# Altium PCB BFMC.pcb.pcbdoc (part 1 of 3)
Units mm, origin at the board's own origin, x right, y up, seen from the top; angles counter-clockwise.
Board outline 121.38 x 89.66 mm, 2 copper layers (Top Layer, Bottom Layer); 106 components, 51 nets, 277 pads, 97 vias.
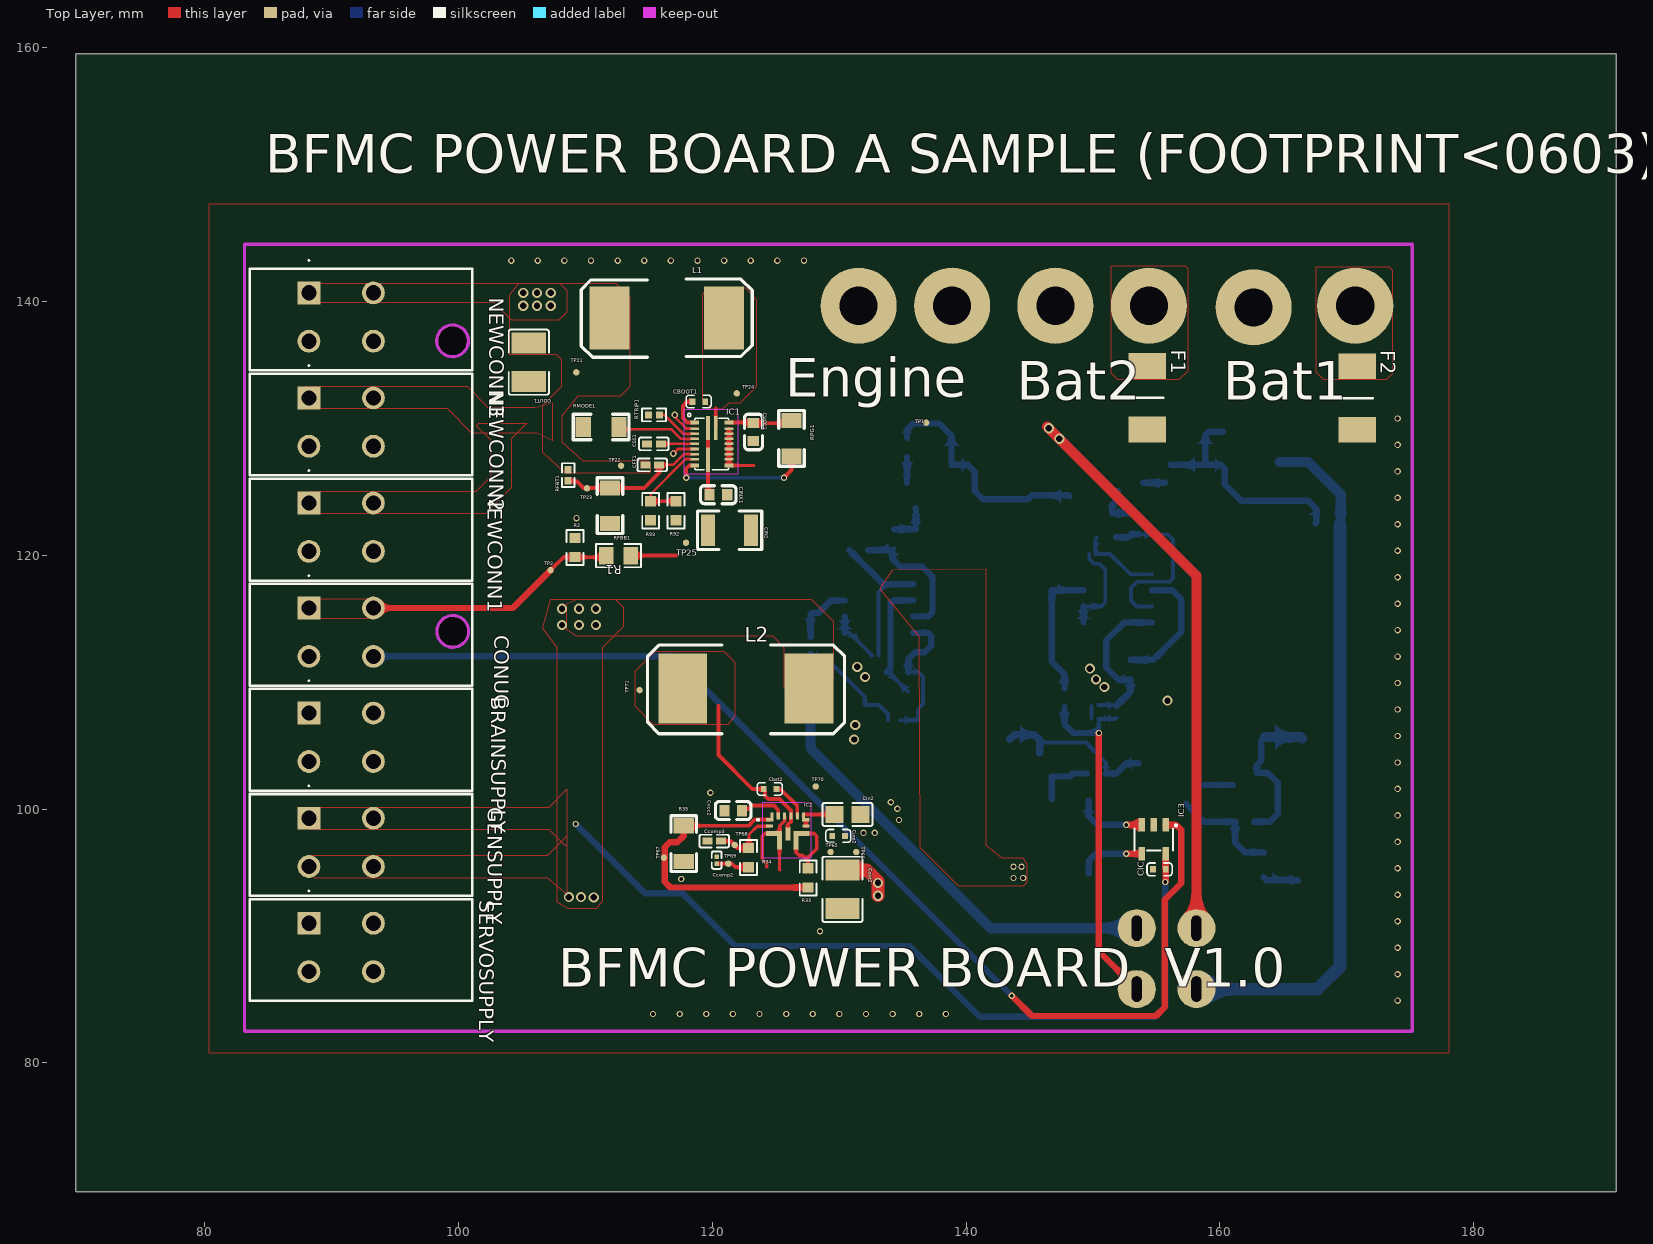
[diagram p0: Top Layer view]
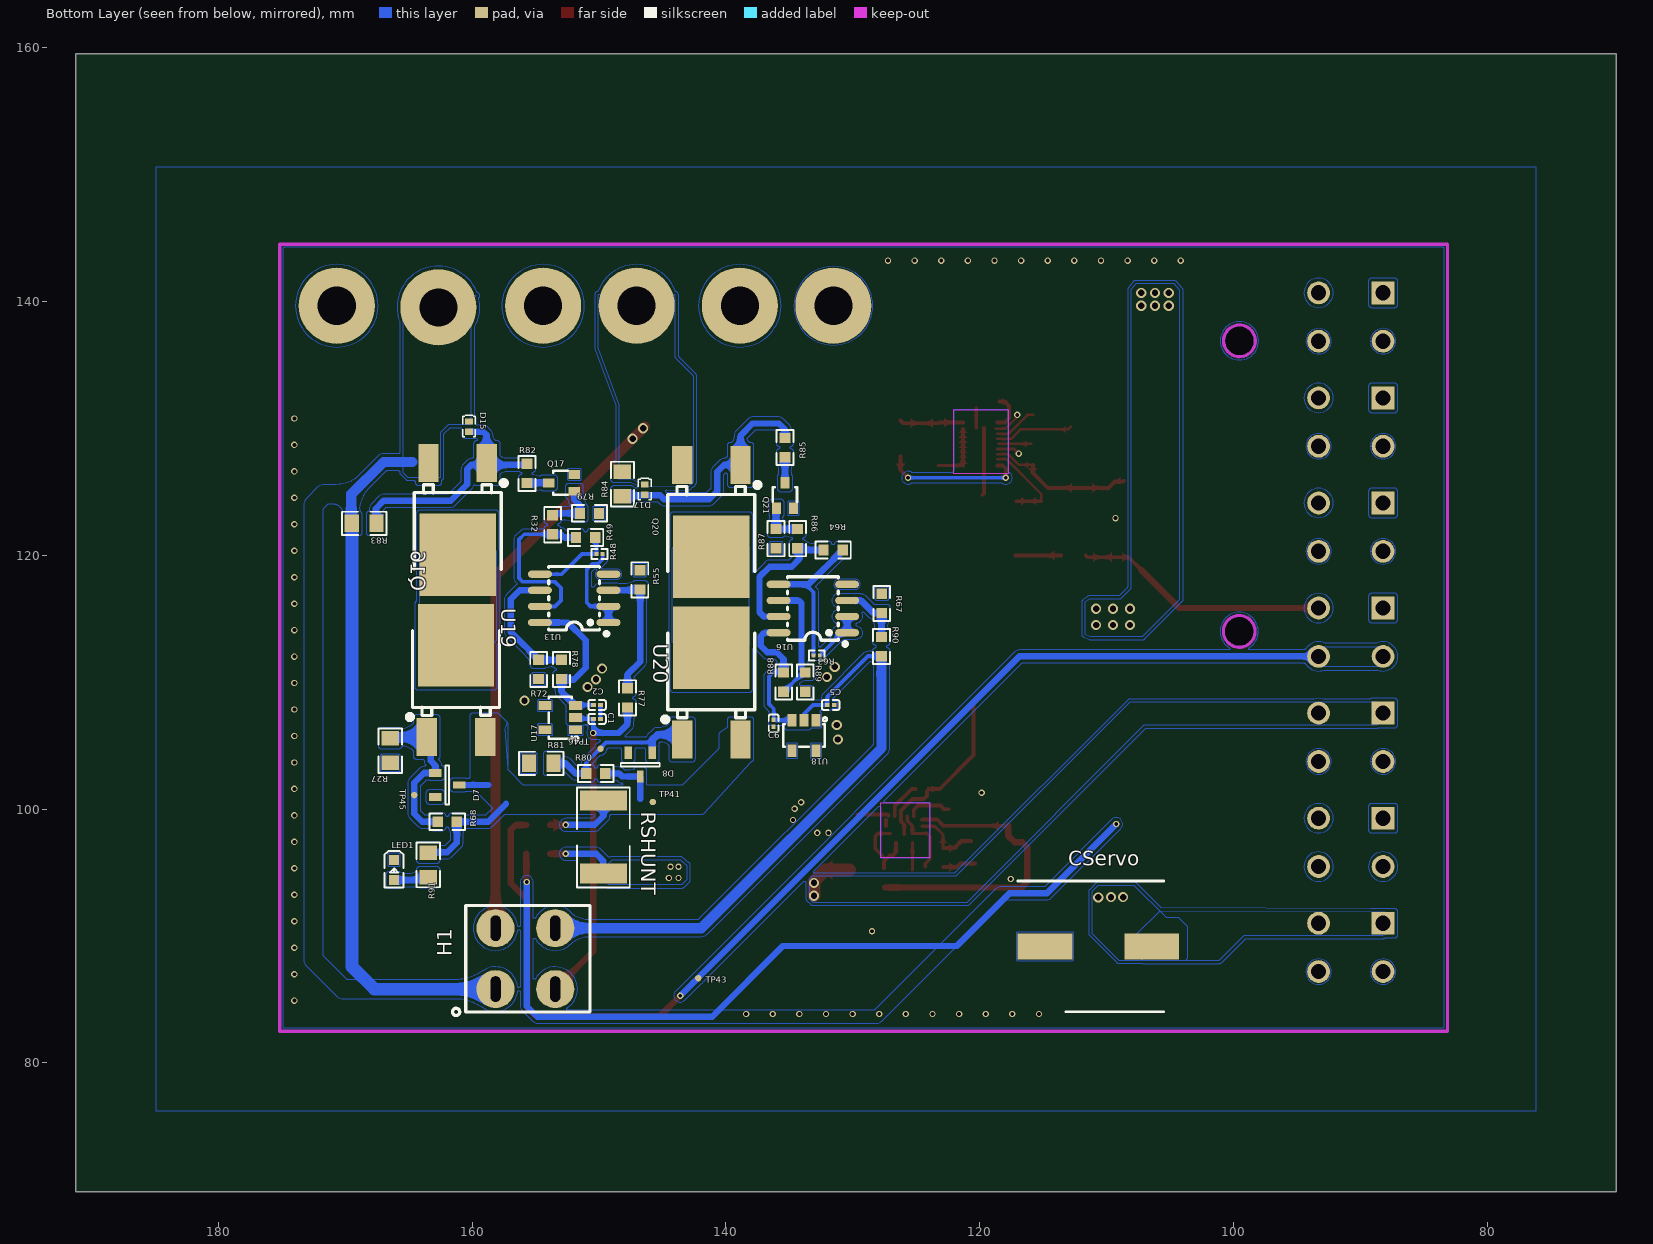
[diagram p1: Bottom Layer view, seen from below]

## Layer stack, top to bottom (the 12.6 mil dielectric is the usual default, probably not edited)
Top Layer: signal copper (thickness not stored)
Dielectric: dielectric 0.32, FR-4, Dk 4.8
Bottom Layer: signal copper (thickness not stored)

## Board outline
191.233,69.85 69.85,69.85 69.85,159.511 191.233,159.511
cut-out: 100.797,136.879 ccw(c99.547,136.867) 98.297,136.879 ccw(c99.547,136.89)
cut-out: 100.814,113.992 ccw(c99.564,113.979) 98.314,113.992 ccw(c99.564,114.004)

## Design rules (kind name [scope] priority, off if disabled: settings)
Clearance copperThickness1oz [All] p1: gap=0.178 ignorepadtopadclearanceinfootprint=FALSE except(0.102: Track-Track; 0.152: Track-SMDPad SMDPad-SMDPad Track-THPad SMDPad-THPad THPad-THPad Track-Via SMDPad-Via THPad-Via Via-Via Track-Fill SMDPad-Fill THPad-Fill Via-Fill Fill-Fill SMDPad-Region THPad-Region Via-Region Fill-Region Region-Region Track-Poly SMDPad-Poly THPad-Poly Via-Poly Fill-Poly Poly-Poly Track-Text SMDPad-Text THPad-Text Via-Text Fill-Text Region-Text Poly-Text Text-Text Track-Hole SMDPad-Hole THPad-Hole Via-Hole Fill-Hole Region-Hole Poly-Hole Text-Hole; 0.3: Track-Region Region-Poly Track-Sheet SMDPad-Sheet THPad-Sheet Via-Sheet Fill-Sheet Region-Sheet Poly-Sheet Text-Sheet Sheet-Hole)
Clearance copperThickness2oz [All] p1: gap=0.178 ignorepadtopadclearanceinfootprint=FALSE except(0.152: Track-SMDPad SMDPad-SMDPad Track-THPad SMDPad-THPad THPad-THPad Track-Via SMDPad-Via THPad-Via Via-Via Track-Fill SMDPad-Fill THPad-Fill Via-Fill Fill-Fill SMDPad-Region THPad-Region Via-Region Fill-Region Region-Region Track-Poly SMDPad-Poly THPad-Poly Via-Poly Fill-Poly Poly-Poly Track-Text SMDPad-Text THPad-Text Via-Text Fill-Text Region-Text Poly-Text Text-Text Track-Hole SMDPad-Hole THPad-Hole Via-Hole Fill-Hole Region-Hole Poly-Hole Text-Hole; 0.203: Track-Track; 0.3: Track-Region Region-Poly Track-Sheet SMDPad-Sheet THPad-Sheet Via-Sheet Fill-Sheet Region-Sheet Poly-Sheet Text-Sheet Sheet-Hole)
Clearance Supply-GND [All] p1: gap=0.178 ignorepadtopadclearanceinfootprint=FALSE except(0.5: Track-Track Track-SMDPad SMDPad-SMDPad Track-THPad SMDPad-THPad THPad-THPad Track-Via SMDPad-Via THPad-Via Via-Via Track-Fill SMDPad-Fill THPad-Fill Via-Fill Fill-Fill Track-Region SMDPad-Region THPad-Region Via-Region Fill-Region Region-Region Track-Poly SMDPad-Poly THPad-Poly Via-Poly Fill-Poly Region-Poly Poly-Poly Track-Text SMDPad-Text THPad-Text Via-Text Fill-Text Region-Text Poly-Text Text-Text Track-Sheet SMDPad-Sheet THPad-Sheet Via-Sheet Fill-Sheet Region-Sheet Poly-Sheet Text-Sheet Track-Hole SMDPad-Hole THPad-Hole Via-Hole Fill-Hole Region-Hole Poly-Hole Text-Hole Sheet-Hole)
DiffPairsRouting differentialPair [All] p1: maxuncoupledlength=10 maxlimit=5.9843 mostfreqgap=5.9843 toplayer_minwidth=5 toplayer_prefwidth=10 toplayer_maxwidth=100 bottomlayer_minwidth=5 bottomlayer_prefwidth=10 bottomlayer_maxwidth=100
PasteMaskExpansion pasteMaskExpansion [All] p1:
PlaneConnect innerPlane [All] p1: planeconnectstyle=Relief reliefexpansion=0.508 reliefentries=4 reliefconductorwidth=0.254 reliefairgap=0.254
PolygonConnect copperRegion [All] p1: connectstyle=Direct reliefentries=4 reliefconductorwidth=10 polygonreliefangle="90 Angle" airgapwidth=10
PolygonConnect copperRegion1 [All] p1: connectstyle=Relief reliefentries=4 reliefconductorwidth=10 polygonreliefangle="90 Angle" airgapwidth=10
PolygonConnect copperRegion2 [All] p1: connectstyle=Relief reliefentries=4 reliefconductorwidth=10 polygonreliefangle="90 Angle" airgapwidth=10
RoutingVias viaSize [All] p1: viastyle="Through Hole" holewidth=12.0078 minholewidth=11.811 maxholewidth=248.0314 width=24.0158 minwidth=19.685 maxwidth=393.7008
SolderMaskExpansion solderMaskExpansion [All] p1: useseparateexpansions=TRUE expansion=2.0079 expansionbottom=2.0079
Width copperThickness1oz [All] p1: maxlimit=100 minlimit=5 preferedwidth=10
Width copperThickness2oz [All] p1: maxlimit=100 minlimit=8 preferedwidth=10

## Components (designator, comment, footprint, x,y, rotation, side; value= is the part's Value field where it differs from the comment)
BRAINSUPPLY "switch" 1704498 88.231,107.554 r270 top
C1 "CAP_0201" c0201 150.151,107.096 r180 bottom
C2 "CAP_0201" c0201 150.151,108.196 r180 bottom
C5 "CAP_0201" c0201 131.751,108.196 r180 bottom
C6 "CAP_0201" C0201 136.237,106.753 r270 bottom
CBOOT1 "EMK105 B7104KVHF" "emk105 b7104kvhf" 118.951,132.096 r0 top
Cbst2 "CAP_0201" "EMK105 B7104KVHF" 124.558,101.575 r0 top
Ccomp2 "CAP_0201" c0201 120.358,95.975 r270 top
Ccomp3 "CAP_0201" c0402 120.158,97.475 r0 top
CFF1 "C1005C0G1H220J" c0402_new 115.277,127.108 r0 top
CIC "C2012X7S1C106K" "emk105 b7104kvhf" 155.22,95.256 r180 top
CIN1 "GCJ31CC71E106K" r1206-1 121.373,121.963 r0 top
Cin2 "CAP_0201" c0805 130.658,99.575 r180 top
CINX1 "GCM188C71A225K" c0603 120.484,124.757 r0 top
Cinx2 "CAP_0201" "emk105 b7104kvhf" 129.958,97.875 r0 top
CONUC "switch" 1704498 88.231,115.831 r270 top
COUT1 "EMK325ABJ107MM-T" c1210 105.551,135.196 r270 top
Cout2 "CAP_0201" c1210 130.258,93.675 r90 top
CServo "GCM188C71A225K" capae1030x1050n 110.665,89.178 r180 bottom
CSS1 "C1608X7R1H154K" c0402_new 115.404,128.759 r180 top
CVCC1 "GCM188C71A225K" c0603 123.251,129.696 r270 top
Cvcc2 "CAP_0201" C0603 121.658,99.875 r0 top
D7 "SZBZX84C18ET1G" szbzx84c18et1g 161.951,101.896 r270 bottom
D8 "SZBZX84C18ET1G" szbzx84c18et1g 146.751,103.496 r0 bottom
D15 "PZU6.8B2L,315" dfn1006-2l-rd 160.24,130.121 r270 bottom
D17 "PZU6.8B2L,315" dfn1006-2l-rd 146.397,125.168 r270 bottom
F1 "0451015.MRL" fusc6127x294n 154.271,132.399 r270 top
F2 "0451015.MRL" fusc6127x294n 170.799,132.372 r270 top
GENSUPPLY "switch" 1704498 88.231,99.277 r270 top
H1 "switch" M2021BB1W01 155.795,88.211 r0 bottom
IC1 "TPS548A28RWWR" TPS548B28RWWR 119.976,128.759 r0 top
IC2 "TPS61288RQQR" TPS61288RQQR 125.958,98.275 r0 top
IC3 "INA180A2QDBVRQ1" ina180a2qdbvrq1 154.779,97.609 r180 top
L1 "IHLP4040DZERR47M11" ihlp4040dzerr47m11 116.42,138.63 r0 top
L2 "L_0402" "dr127-3r3-r (l2)" 122.658,109.488 r0 top
LED1 "19-213/Y2C-CQ2R2L/3T(CY)" led0603-rd-yellow 166.151,95.196 r270 bottom
NEWCONN1 "switch" 1704498 88.231,124.108 r270 top
NEWCONN2 "switch" 1704498 88.231,132.385 r270 top
NEWCONN3 "switch" 1704498 88.231,140.662 r270 top
Q16 "IPD50P04P4-13" pg-to252-3_l6.3-w6.5-p4.57-ls10.0-br-cw 161.129,123.644 r90 bottom
Q17 "BC846W" sot-323-3_l2.2-w1.3-p1.30-ls2.2-br 152.951,125.696 r180 bottom
Q20 "IPD50P04P4-13" pg-to252-3_l6.3-w6.5-p4.57-ls10.0-br-cw 141.151,123.496 r90 bottom
Q21 "BC846W" sot-323-3_l2.2-w1.3-p1.30-ls2.2-br 135.351,124.696 r270 bottom
R1 "MCR03..PFX1051" R0805_NEW 112.615,119.961 r0 top
R2 "MCR03...PFX7680" r0603_new 109.186,120.596 r90 top
R27 "MCR03..PFX1002" r0805_new 166.451,104.596 r270 bottom
R32 "MCR03..PFX1002" R0603 153.651,122.396 r90 bottom
R33 "MCR03..PFX1002" r0603 127.558,94.575 r90 top
R34 "MCR03..PFX1002" R0603 122.858,96.175 r90 top
R35 "MCR03..PFX1002" r0204 117.758,97.275 r270 top
R48 "Res_0603" R0201 149.951,120.096 r0 bottom
R49 "Res_0603" R0603 151.051,121.396 r0 bottom
R55 "Res_0603" r0603 146.778,118.056 r270 bottom
R63 "Res_0603" R0201 132.851,112.096 r0 bottom
R64 "Res_0603" R0603 131.551,120.396 r0 bottom
R67 "Res_0603" r0603 127.724,116.196 r270 bottom
R68 "Res_0603" r0603 161.951,98.996 r180 bottom
R72 "Res_0603" r0603 154.751,110.996 r270 bottom
R77 "Res_0603" R0603 147.751,108.758 r270 bottom
R78 "Res_0603" R0603 152.951,110.996 r270 bottom
R79 "Res_0603" r0603 150.751,123.296 r0 bottom
R80 "Res_0603" r0603 150.251,102.796 r180 bottom
R81 "MCR03..PFX1002" r0805_new 154.551,103.596 r0 bottom
R82 "Res_0603" R0603 155.668,126.438 r90 bottom
R83 "MCR03..PFX1002" R0805_NEW 168.495,122.501 r0 bottom
R84 "MCR03..PFX1002" r0805_new 148.151,125.596 r90 bottom
R85 "Res_0603" R0603 135.348,128.47 r90 bottom
R86 "MCR03..PFX1002" R0603 134.351,121.296 r270 bottom
R87 "Res_0603" r0603 136.051,121.296 r90 bottom
R88 "Res_0603" R0603 135.451,109.996 r270 bottom
R89 "Res_0603" r0603 133.751,109.996 r270 bottom
R90 "Res_0603" R0603 127.751,112.796 r90 bottom
R91 "Res_0603" r0805_new 163.451,95.596 r90 bottom
R92 "Res_0603" r0603 117.151,123.496 r270 top
R93 "Res_0603" r0603 115.151,123.496 r90 top
RFBB1 "SMM0204 50 10K 1 %" r0204 111.951,123.896 r270 top
RFBT1 "SMM0204 50 73K2 1 %" r0402 108.651,126.296 r270 top
RMODE1 "SMM0204 50 30K1 1 %" r0204 111.251,130.096 r180 top
RPG1 "SMM0204 50 30K1 1 %" R0204 126.251,129.196 r90 top
RSHUNT "WSLP25122L500FEA" "wslp25122l000fea bun" 149.651,97.796 r270 bottom
RTRIP1 "SMM0204 50 7K32 1 %" r0402 115.404,131.045 r180 top
SERVOSUPPLY "switch" 1704498 88.231,91.001 r270 top
TP1 "Test-Point" test-point-0.5mm 136.856,130.438 r180 top
TP2 "Test-Point" Test-Point-0.5mm 107.267,118.818 r0 top
TP21 "Test-Point" test-point-0.5mm 109.296,134.4 r0 top
TP22 "Test-Point" test-point-0.5mm 112.825,127.043 r0 top
TP23 "Test-Point" Test-Point-0.5mm 110.134,125.265 r90 top
TP24 "Test-Point" test-point-0.5mm 121.938,132.742 r270 top
TP25 "Test-Point" test-point-0.5mm 117.938,120.977 r0 top
TP41 "Test-Point" test-point-0.5mm 145.759,100.554 r180 bottom
TP43 "Test-Point" Test-Point-0.5mm 142.178,86.672 r180 bottom
TP45 "Test-Point" Test-Point-0.5mm 164.551,101.096 r180 bottom
TP46 "Test-Point" Test-Point-0.5mm 149.878,104.75 r180 bottom
TP65 "Test-Point" test-point-0.5mm 129.326,96.615 r0 top
TP66 "Test-Point" test-point-0.5mm 131.35,96.612 r270 top
TP67 "Test-Point" Test-Point-0.5mm 116.197,96.166 r0 top
TP68 "Test-Point" Test-Point-0.5mm 121.773,97.166 r0 top
TP69 "Test-Point" Test-Point-0.5mm 121.27,95.691 r0 top
TP70 "Test-Point" test-point-0.5mm 128.158,101.775 r270 top
TP71 "Test-Point" test-point-0.5mm 114.282,109.367 r0 top
U13 "LT1490IS8#PBF" so-8_l4.9-w3.9-p1.27-ls5.9-bl 151.951,116.596 r90 bottom
U16 "LT1490IS8#PBF" so-8_l4.9-w3.9-p1.27-ls5.9-bl 133.151,115.796 r90 bottom
U17 "NCP715SN50T1G" tsop-5_l3.0-w1.5-p0.95-bl 153.051,107.196 r90 bottom
U18 "NCP715SN50T1G" tsop-5_l3.0-w1.5-p0.95-bl 133.851,105.796 r0 bottom
U19 "DMPH3010LK3-13" pg-to252-3_l6.3-w6.5-p4.57-ls10.0-br-cw 161.266,109.282 r270 bottom
U20 "DMPH3010LK3-13" pg-to252-3_l6.3-w6.5-p4.57-ls10.0-br-cw 141.151,109.096 r270 bottom

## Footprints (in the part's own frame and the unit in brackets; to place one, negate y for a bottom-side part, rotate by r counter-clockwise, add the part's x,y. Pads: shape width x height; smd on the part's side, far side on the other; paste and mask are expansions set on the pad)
1704498 [mm]
  rect 1.8x1.8 hole 1.2: 1(0,0)
  round 1.8 hole 1.2: 2(0,5.08) 3(3.81,0) 4(3.81,5.08)
  silkscreen extent -2.6,-4.65 6.11,12.85
c0201 [mm]
  rect 0.368x0.324 smd: 1(-0.274,0) 2(0.274,0)
  silkscreen extent -0.69,-0.39 0.69,0.39
C0201 [mm]
  rect 0.368x0.324 smd: 1(-0.274,0) 2(0.274,0)
  silkscreen extent -0.69,-0.39 0.69,0.39
c0402 [mm]
  rect 0.79x0.54 smd: 1(-0.545,0) 2(0.545,0)
  silkscreen extent -1.17,-0.5 1.17,0.5
c0402_new [mm]
  rect 0.79x0.54 smd: 1(-0.545,0) 2(0.545,0)
  silkscreen extent -1.17,-0.5 1.17,0.5
c0603 [mm]
  rect 0.8x0.9 smd: 1(-0.7,0) 2(0.7,0)
  silkscreen extent -1.41,-0.71 1.39,0.72
C0603 [mm]
  rect 0.8x0.9 smd: 1(-0.7,0) 2(0.7,0)
  silkscreen extent -1.41,-0.71 1.39,0.72
c0805 [mm]
  rect 1.41x1.35 smd: 1(-1.03,0) 2(1.03,0)
  silkscreen extent -1.96,-0.9 1.96,0.9
c1210 [mm]
  rect 1.635x2.7 smd: 1(-1.517,0) 2(1.517,0)
  silkscreen extent -2.56,-1.58 2.56,1.58
capae1030x1050n [mm]
  rect 4.3x2.05 smd: 1(-4.2,0) 2(4.2,0)
  silkscreen extent -6.35,-5.15 5.15,5.15
dfn1006-2l-rd [mm]
  rect 0.5x0.6 smd: 1(-0.4,0) 2(0.4,0)
  silkscreen extent -0.9,-0.5 0.8,0.5
"dr127-3r3-r (l2)" [mm]
  rect 3.85x5.5 smd: 1(-4.975,0) 2(4.975,0)
  silkscreen extent -7.75,-3.56 7.77,3.43
"emk105 b7104kvhf" [mm]
  rect 0.45x0.5 smd: 1(-0.5,0) 2(0.5,0)
  silkscreen extent -1.01,-0.49 0.97,0.51
"EMK105 B7104KVHF" [mm]
  rect 0.45x0.5 smd: 1(-0.5,0) 2(0.5,0)
  silkscreen extent -1.01,-0.49 0.97,0.51
fusc6127x294n [mm]
  rect 2.02x2.95 smd: 1(-2.5,0) 2(2.5,0)
  silkscreen extent 0,-1.24 0,1.24
ihlp4040dzerr47m11 [mil]
  rect 125x195 smd: 1(-177.5,2.5) 2(177.5,2.5)
  silkscreen extent -265,-120 265,122
ina180a2qdbvrq1 [mm]
  rect 0.532x1.07 smd: 1(-0.95,-1.135) 2(0,-1.135) 3(0.95,-1.135) 4(0.95,1.135) 5(-0.95,1.135)
  silkscreen extent -1.9,-1.25 1.53,0.88
led0603-rd-yellow [mm]
  rect 0.8x0.8 smd: 1(-0.799,-0.003) 2(0.799,0.003)
  silkscreen extent -1.49,-0.75 1.39,0.76
M2021BB1W01 [mm]
  round 3 hole 0.8 slot 2 at 90 deg: 1(-2.35,-2.4) 2(2.35,-2.4) 3(-2.35,2.4) 4(2.35,2.4)
  silkscreen extent -5.08,-4.19 5.74,4.47
pg-to252-3_l6.3-w6.5-p4.57-ls10.0-br-cw [mm]
  rect 3x1.6 smd: 1(3.614,-2.299) 3(3.614,2.299)
  rect 6.5x6 smd: 2(-3.614,0.001)
  silkscreen extent -4.76,-3.83 2.24,3.43
R0201 [mm]
  rect 0.303x0.324 smd: 1(-0.242,0) 2(0.242,0)
  silkscreen extent -0.62,-0.39 0.62,0.39
r0204 [mm]
  rect 1.2x1.6 smd: 1(-1.4,0) 2(1.4,0)
  silkscreen extent -2.2,-1 2.2,1
R0204 [mm]
  rect 1.2x1.6 smd: 1(-1.4,0) 2(1.4,0)
  silkscreen extent -2.2,-1 2.2,1
r0402 [mm]
  rect 0.566x0.54 smd: 1(-0.433,0) 2(0.433,0)
  silkscreen extent -0.94,-0.5 0.94,0.5
R0603 [mm]
  rect 0.806x0.864 smd: 1(-0.753,0) 2(0.753,0)
  silkscreen extent -1.39,-0.66 1.39,0.66
r0603 [mm]
  rect 0.806x0.864 smd: 1(-0.753,0) 2(0.753,0)
  silkscreen extent -1.39,-0.66 1.39,0.66
r0603_new [mm]
  rect 0.806x0.864 smd: 1(-0.753,0) 2(0.753,0)
  silkscreen extent -1.39,-0.66 1.39,0.66
R0805_NEW [mm]
  rect 1.133x1.377 smd: 1(-0.966,0) 2(0.966,0)
  silkscreen extent -1.76,-0.92 1.76,0.92
r0805_new [mm]
  rect 1.133x1.377 smd: 1(-0.966,0) 2(0.966,0)
  silkscreen extent -1.76,-0.92 1.76,0.92
r1206-1 [mm]
  rect 1.1x2.5 smd: 1(-1.7,0) 2(1.7,0)
  silkscreen extent -2.54,-1.52 2.54,1.52
so-8_l4.9-w3.9-p1.27-ls5.9-bl [mm]
  oval 0.574x1.888 smd: 1(-1.905,-2.699) 2(-0.635,-2.699) 3(0.635,-2.699) 4(1.905,-2.699) 5(1.905,2.699) 6(0.635,2.699) 7(-0.635,2.699) 8(-1.905,2.699)
  silkscreen extent -2.94,-2.69 2.5,2
sot-323-3_l2.2-w1.3-p1.30-ls2.2-br [mm]
  rect 0.9x0.7 smd: 1(1.016,-0.66) 2(1.016,0.66) 3(-1.016,0)
  silkscreen extent -0.65,-0.95 0.48,0.95
szbzx84c18et1g [mm]
  rect 0.61x0.975 smd: 1(-0.95,-0.937) 2(0.95,-0.937)
  rect 0.523x0.975 smd: 3(0,0.937)
  silkscreen extent -1.54,-0.14 1.54,0.14
test-point-0.5mm [mm]
  round 0.5 smd: 1(0,0)
Test-Point-0.5mm [mm]
  round 0.5 smd: 1(0,0)
TPS548B28RWWR [mm]
  rect 0.7x0.3 smd: 1(-1.35,1.7) 9(-1.35,-1.7) 11(1.35,-1.7) 19(1.35,1.7)
  rect 0.7x0.2 smd: 2(-1.35,1.2) 3(-1.35,0.8) 4(-1.35,0.4) 5(-1.35,0) 6(-1.35,-0.4) 7(-1.35,-0.8) 8(-1.35,-1.2) 12(1.35,-1.2) 13(1.35,-0.8) 14(1.35,-0.4) 15(1.35,0) 16(1.35,0.4) 17(1.35,0.8) 18(1.35,1.2)
  rect 0.3x1.9 smd: 10(-0.3,-1.25) 20(0.3,1.25) 21(-0.3,1.25)
  silkscreen extent -1.9,-2.03 1.32,2.41
TPS61288RQQR [mm]
  rect 0.575x0.25 smd: 1(-1.413,0.875) 7(1.413,0.875)
  rect 0.55x0.25 smd: 2(-1.425,0.375) 6(1.425,0.375)
  rect 1.25x0.4 smd: 3(-1.075,-0.2) 5(1.075,-0.2)
  rect 0.4x1 smd: 4(0,-0.25)
  rect 0.25x0.55 smd: 8(0.75,1.175) 9(0.25,1.175) 10(-0.25,1.175) 11(-0.75,1.175)
  rect 0.225x0.45 smd: 12(-1.237,1.225) 15(1.237,1.225)
  rect 0.4x1.05 smd: 13(-0.65,-0.925) 14(0.65,-0.925)
  silkscreen extent -2.4,0.83 -2.3,0.92
tsop-5_l3.0-w1.5-p0.95-bl [mm]
  rect 0.7x1 smd: 1(-0.95,-1.2) 2(0,-1.2) 3(0.95,-1.2) 4(0.95,1.2) 5(-0.95,1.2)
  silkscreen extent -1.8,-1.42 1.65,0.89
"wslp25122l000fea bun" [mm]
  rect 1.6x3.68 smd: 1(-2.875,0) 2(2.875,0)
  silkscreen extent -3.91,-2.07 3.96,2.07

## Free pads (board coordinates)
  round 6 hole 3: 22(131.538,139.646) 22(138.904,139.646) 22(147.032,139.646) 22(154.398,139.646) 22(162.653,139.519) 22(170.654,139.646)

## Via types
v1: diameter 0.5, hole 0.3, Top Layer to Bottom Layer, 70 vias
v2: diameter 0.8, hole 0.5, Top Layer to Bottom Layer, 27 vias

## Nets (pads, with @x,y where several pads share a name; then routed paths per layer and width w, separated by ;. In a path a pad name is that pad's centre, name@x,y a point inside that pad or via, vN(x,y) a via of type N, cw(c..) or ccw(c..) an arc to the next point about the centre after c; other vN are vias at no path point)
$1N1788: D8.1 R80.1 R81.1 TP46.1 U20.1 | length 13.6
  Bottom Layer w0.3: D8.1@145.802,104.76 145.801,104.974 146.056,105.229 149.445,105.229 151.005,103.669 R80.1@151.005,102.796
  Bottom Layer w0.5: R80.1@151.005,102.796 151.838,102.796 152.638,103.596 R81.1@153.585,103.596
  Bottom Layer w0.6: U20.1@143.451,105.482 143.833,105.864 145.381,105.864 145.802,105.444 145.802,104.974 145.802,104.76 D8.1@145.802,104.433
$1N1798: D7.1 R27.1 R68.1 TP45.1 U19.1 | length 12.6
  Bottom Layer w0.5: R68.1@162.705,98.996 163.913,98.996 164.551,99.634 TP45.1@164.551,101.096 164.551,102.061 163.766,102.846 D7.1@162.889,102.846 162.889,103.432 163.265,103.809 163.265,105.368 U19.1@163.565,105.668
  Bottom Layer w0.8: U19.1@163.565,105.668 166.345,105.668 R27.1@166.451,105.562
$1N2164: Q16.2 U19.2
$1N2337: D15.2 Q16.1 R82.2 R83.1 | length 18.5
  Bottom Layer w0.3: 158.843,129.467 158.852,129.458
  Bottom Layer w0.5: 156.112,127.11 160.038,127.11 160.367,126.78 160.367,125.594 161.683,124.279 166.971,124.279 167.585,123.665 167.585,122.557 R83.1@167.529,122.501 ; Q16.1@158.83,127.258 158.852,127.28 158.852,129.458 159.115,129.721 D15.2@160.24,129.721
$1N2412: Q17.3 R82.1 | length 1.7
  Bottom Layer w0.5: Q17.3@153.967,125.696 155.657,125.696 R82.1@155.668,125.684
$1N2516: Q17.1 R32.2 R79.2 | length 4
  Bottom Layer w0.5: Q17.1@151.935,125.035 151.935,124.38 151.505,123.949 R79.2@151.505,123.296 153.405,123.296 R32.2@153.551,123.149
$1N20674: R55.2 R77.1 U13.3 | length 10.6
  Bottom Layer w0.5: R77.1@147.751,109.511 147.751,110.606 146.751,111.606 146.751,117.231 U13.3@149.252,117.231
$1N20931: R48.1 U13.1 U13.2 | length 7.7
  Bottom Layer w0.3: U13.2@149.252,115.961 150.669,115.961 150.969,116.261 150.969,118.861 150.505,119.326 150.08,119.326 149.71,119.696 R48.1@149.71,120.096
  Bottom Layer w0.5: U13.1@149.252,114.691 U13.2@149.252,115.961
$1N20946: R48.2 R49.1 U13.5 | length 6.5
  Bottom Layer w0.3: R49.1@150.298,121.396 150.193,121.291 R48.2@150.193,120.096 151.342,120.096 152.937,118.501 U13.5@154.65,118.501
$1N20962: R32.1 R49.2 U13.7 | length 14.3
  Bottom Layer w0.3: R32.1@153.651,121.642 155.892,121.642 156.303,121.231 156.303,118.196 156.003,117.896 153.471,117.896 153.001,117.426 153.001,116.42 153.46,115.961 U13.7@154.65,115.961
  Bottom Layer w0.5: R49.2@151.805,121.396 152.751,121.396 152.998,121.642 R32.1@153.651,121.642
$1N21052: R72.1 R78.1 U13.6 | length 10.1
  Bottom Layer w0.5: R78.1@152.951,111.749 R72.1@154.751,111.749 156.951,113.949 156.951,116.519 156.239,117.231 U13.6@154.65,117.231
$1N27791: Q20.2 U20.2
$1N27792: D17.2 Q20.1 R84.1 R85.2 | length 18.5
  Bottom Layer w0.5: R85.2@135.348,129.223 135.348,129.875 135.848,130.375 137.888,130.375 138.852,129.411 Q20.1@138.852,127.11 140.137,127.11 140.682,126.565 140.682,125.041 141.317,124.406 144.873,124.406 145.173,124.706 148.075,124.706 R84.1@148.151,124.629
$1N27793: Q21.3 R85.1 | length 2
  Bottom Layer w0.5: R85.1@135.348,127.716 135.351,127.713 Q21.3@135.351,125.712
$1N27799: Q21.1 R86.1 R87.2 | length 3.3
  Bottom Layer w0.5: R86.1@134.351,122.049 R87.2@136.051,122.049 136.051,123.64 Q21.1@136.012,123.68
$1N27802: R63.1 U16.1 U16.2 | length 4.2
  Bottom Layer w0.3: U16.1@130.452,113.891 130.815,113.891 R63.1@132.61,112.096
  Bottom Layer w0.5: U16.1@130.452,113.891 U16.2@130.452,115.161
$1N27807: R63.2 R64.1 U16.5 | length 14.2
  Bottom Layer w0.3: R63.2@133.093,112.096 133.093,117.07 133.718,117.696 135.845,117.696 U16.5@135.85,117.701
  Bottom Layer w0.5: R64.1@130.798,120.396 133.493,117.701 U16.5@135.85,117.701
$1N27811: R64.2 R86.2 U16.7 | length 11
  Bottom Layer w0.3: R86.2@134.205,120.396 R86.2@134.351,120.542
  Bottom Layer w0.5: R64.2@132.305,120.396 134.205,120.396 134.2,120.391 134.2,119.712 134.816,119.096 136.551,119.096 137.351,118.296 137.351,115.487 137.025,115.161 U16.7@135.85,115.161
$1N27822: R67.2 R90.2 U16.3 | length 4.9
  Bottom Layer w0.3: R67.2@127.751,115.342 R67.2@127.851,115.442
  Bottom Layer w0.5: R90.2@127.751,113.549 R67.2@127.751,115.342 ; R67.2@127.851,115.442 128.37,115.442 129.358,116.431 U16.3@130.452,116.431
$1N32332: R88.2 R89.1 U16.6 | length 9.8
  Bottom Layer w0.3: R89.1@133.751,110.749 133.945,110.749 R88.2@135.451,109.242
  Bottom Layer w0.5: R89.1@133.751,110.749 134.051,111.049 134.051,116.196 134.286,116.431 U16.6@135.85,116.431
$1N40141: LED1.2 R91.1 | length 2.8
  Bottom Layer w0.5: R91.1@163.451,94.629 163.685,94.396 LED1.2@166.148,94.396
$2N28: F1.1 pad.22@154.398,139.646
$2N30: F2.1 pad.22@170.654,139.646
$3N2936: Ccomp2.2 R34.1 TP69.1 | length 2.8
  Top Layer w0.3: Ccomp2.2@120.358,95.7 TP69.1@121.47,95.7 ; TP69.1@121.27,95.691 121.57,95.691 121.84,95.421 R34.1@122.858,95.421
+5V: CFF1.1 CIC.1 Cin2.2 Cinx2.1 COUT1.1 CServo.2 GENSUPPLY.1 GENSUPPLY.2 GENSUPPLY.3 GENSUPPLY.4 IC2.6 IC2.7 IC2.15 IC3.5 L1.1 L2.2 NEWCONN1.1 NEWCONN1.2 NEWCONN2.1 NEWCONN2.2 NEWCONN3.1 NEWCONN3.2 RFBT1.1 SERVOSUPPLY.1 SERVOSUPPLY.2 TP21.1 TP22.1 TP70.1 | length 68.1
  Top Layer w0.3: IC2.15@127.195,99.5 127.27,99.575 Cin2.2@129.628,99.575 ; IC2.7@127.371,99.15 127.383,99.138 IC2.6@127.383,98.65
  Top Layer w0.5: v1(155.691,94.256) 155.72,94.285 CIC.1@155.72,95.256 155.72,96.465 IC3.5@155.729,96.474
  Bottom Layer w0.5: v1(109.251,98.816) 114.711,93.356 117.657,93.356 121.808,89.204 135.518,89.204 141.087,83.636 154.851,83.636 155.691,84.476 v1(155.691,94.256)
  other v2: 110.665,93.042 108.711,93.056 109.668,93.056 108.17,114.5 109.504,114.5 110.837,114.5 108.17,115.77 109.504,115.77 110.837,115.77 105.122,139.646 106.202,139.646 107.281,139.646 105.122,140.662 106.202,140.662 107.281,140.662
+VCC2: C2.1 R78.2 U13.8 U17.3 | length 12.7
  Bottom Layer w0.3: C2.1@150.426,108.196 151.801,108.196 U17.3@151.851,108.146
  Bottom Layer w0.5: U17.3@151.851,108.146 152.951,109.246 R78.2@152.951,110.242 152.891,110.182 151.985,110.182 151.051,111.116 151.051,113.296 152.446,114.691 U13.8@154.65,114.691
+VCC3: C6.1 R88.1 U16.8 U18.3 | length 11.9
  Bottom Layer w0.3: U18.3@134.801,106.996 136.206,106.996 C6.1@136.237,107.027 136.237,107.896 136.618,108.277 136.618,110.436 136.237,110.817 135.519,110.817 R88.1@135.451,110.749
  Bottom Layer w0.5: R88.1@135.451,110.749 135.451,111.809 135.983,112.341 136.745,112.341 137.253,112.849 137.253,113.611 136.999,113.865 135.876,113.865 U16.8@135.85,113.891
ADC1: CONUC.1 CONUC.2 R1.1 R2.1 TP2.1 | length 20
  Top Layer w0.3: TP2.1@107.267,118.818 108.283,119.834 111.522,119.834 R1.1@111.649,119.961
  Top Layer w0.5: CONUC.2@93.311,115.831 104.281,115.831 TP2.1@107.267,118.818
BOOT: CBOOT1.1 IC1.1 | length 2.9
  Top Layer w0.3: CBOOT1.1@118.451,132.096 118.027,132.096 117.69,131.759 117.69,130.791 118.022,130.459 IC1.1@118.626,130.459
BST: Cbst2.2 IC2.8 | length 3
  Top Layer w0.3: Cbst2.2@125.058,101.575 125.358,101.575 126.708,100.225 IC2.8@126.708,99.45
COMP: Ccomp3.2 IC2.2 R34.2 TP68.1 | length 5.4
  Top Layer w0.254: R34.2@122.858,96.928 122.902,96.972 122.902,97.99 123.562,98.65 IC2.2@124.533,98.65
  Top Layer w0.3: Ccomp3.2@120.704,97.475 121.458,97.475 122.005,96.928 R34.2@122.858,96.928
EN: IC1.8 R92.1 R93.2 | length 7.2
  Top Layer w0.2: R93.2@115.151,124.249 115.151,124.796 117.914,127.559 IC1.8@118.626,127.559
  Top Layer w0.254: R93.2@115.151,124.249 R92.1@117.151,124.249
FB: CFF1.2 IC1.7 RFBB1.1 RFBT1.2 TP23.1 | length 11.7
  Top Layer w0.2: CFF1.2@115.823,127.108 116.928,127.108 117.779,127.959 IC1.7@118.626,127.959
  Top Layer w0.3: RFBT1.2@108.651,125.863 108.719,125.796 109.351,125.796 109.851,125.296 RFBB1.1@111.951,125.296 114.651,125.296 115.823,126.467 CFF1.2@115.823,127.108
FB_1: IC2.1 IC2.12 R33.1 R35.1 TP67.1 | length 23.6
  Top Layer w0.3: R35.1@117.958,98.675 122.858,98.675 123.358,99.175 124.52,99.175 IC2.1@124.545,99.15
  Top Layer w0.5: R35.1@117.758,98.675 117.758,97.875 117.258,97.375 116.658,97.375 116.258,96.975 116.258,94.275 116.712,93.821 R33.1@127.458,93.821
GND: 
ISHUNT: CONUC.3 CONUC.4 IC3.1 TP43.1 | length 90.3
  Top Layer w0.5: v1(143.603,85.29) 145.197,83.696 154.963,83.696 155.651,84.384 155.651,92.865 156.938,94.152 156.938,98.371 156.565,98.744 IC3.1@155.729,98.744
  Bottom Layer w0.3: TP43.1@142.178,86.672 TP43.1@142.221,86.672
  Bottom Layer w0.5: CONUC.4@93.311,112.021 116.872,112.021 142.221,86.672 v1(143.603,85.29)
MODE: IC1.4 RMODE1.1 | length 6.2
  Top Layer w0.2: RMODE1.1@112.851,130.096 113.045,129.902 116.801,129.902 117.544,129.159 IC1.4@118.626,129.159
OUT_BATT: CIN1.1 CINX1.1 IC1.10 IC1.21 IC3.4 pad.22@138.904,139.646 R1.2 R92.2 RSHUNT.2 TP1.1 TP25.1 | length 14.3
  Top Layer w0.3: R1.2@113.582,119.961 117.187,119.961 ; IC1.21@119.676,130.009 IC1.10@119.676,127.509 119.676,124.865 CINX1.1@119.784,124.757
  Top Layer w0.5: v1(152.62,96.474) IC3.4@153.829,96.474
  Bottom Layer w0.5: RSHUNT.2@149.651,94.921 149.651,95.91 150.215,96.474 v1(152.62,96.474)
  other v1: 143.73,94.561 144.492,94.561 143.73,95.45 144.365,95.45
OUT_BATT1: D15.1 H1.4 pad.22@162.653,139.519 Q16.3 R83.2 | length 54.6
  Bottom Layer w0.8: 164.685,127.327 166.981,127.327 169.518,124.79 R83.2@169.518,122.996
  Bottom Layer w1: H1.4@158.145,85.811 167.695,85.811 169.459,87.574 R83.2@169.459,122.438
OUT_BATT2: D17.1 H1.2 pad.22@147.032,139.646 Q20.3 R84.2 | length 44.4
  Top Layer w0.8: v2@146.397,130.121 v2(147.351,129.167) 158.145,118.373 H1.2@158.145,90.611
  other v2: 146.524,129.994
PGOOD: IC1.9 RPG1.1 | length 11.1
  Top Layer w0.3: v1@117.944,126.112 117.944,126.805 118.198,127.059 IC1.9@118.626,127.059 ; v1(125.651,126.096) 126.251,126.696 RPG1.1@126.251,127.796
  Bottom Layer w0.3: v1(117.951,126.096) v1(125.651,126.096)
SS_REFIN: CSS1.1 IC1.5 | length 2.5
  Top Layer w0.2: CSS1.1@115.95,128.759 IC1.5@118.499,128.759
SW: CBOOT1.2 IC1.20 L1.2 TP24.1 | length 1.6
  Top Layer w0.254: IC1.20@120.276,130.009 120.276,131.596
SW_1: Cbst2.1 IC2.4 IC2.9 L2.1 TP71.1 | length 13.4
  Top Layer w0.3: 120.489,108.13 120.489,104.244 123.158,101.575 Cbst2.1@124.058,101.575 ; Cbst2.1@124.158,101.375 124.172,101.361 124.172,101.038 124.426,100.784 125.299,100.784 126.208,99.875 IC2.9@126.208,99.45 126.208,99.025 125.958,98.775 IC2.4@125.958,98.025
TRIP: IC1.3 RTRIP1.1 | length 3.4
  Top Layer w0.2: RTRIP1.1@115.806,131.045 116.258,131.045 117.744,129.559 IC1.3@118.626,129.559
UBATT: D7.3 D8.3 IC3.3 R68.2 R80.2 R91.2 RSHUNT.1 TP41.1 U19.3 U20.3 | length 21.3
  Top Layer w0.5: v1(152.62,98.752) 153.821,98.752 IC3.3@153.829,98.744
  Bottom Layer w0.5: 146.751,100.784 D8.3@146.751,102.558 148.172,102.558 148.409,102.796 R80.2@149.498,102.796 ; RSHUNT.1@149.651,100.671 149.651,99.435 150.334,98.752 v1(152.62,98.752) ; 157.319,100.403 158.726,98.996 R68.2@161.198,98.996 161.198,97.349 161.951,96.596 163.418,96.596 R91.2@163.451,96.562 ; 158.716,101.896 D7.3@161.014,101.896
VBATT1: C1.1 H1.3 R77.2 U17.2 | length 28.3
  Top Layer w0.5: v1(150.461,105.991) 150.461,88.795 H1.3@153.445,85.811
  Bottom Layer w0.3: v1(150.461,105.991) 150.461,107.06 C1.1@150.426,107.096 151.751,107.096 U17.2@151.851,107.196
  Bottom Layer w0.5: R77.2@147.751,108.004 147.751,106.669 148.429,105.991 v1(150.461,105.991)
VBATT2: C5.1 H1.1 R90.1 U18.2 | length 47.7
  Bottom Layer w0.3: R90.1@127.751,112.042 128.805,112.042 132.026,108.821 C5.1@132.026,108.196 133.151,108.196 133.851,107.496 U18.2@133.851,106.996
  Bottom Layer w0.8: R90.1@127.751,112.042 127.751,104.796 141.936,90.611 H1.1@153.445,90.611
VCC: CVCC1.1 IC1.19 RPG1.2 | length 5
  Top Layer w0.3: IC1.19@121.326,130.459 123.189,130.459 CVCC1.1@123.252,130.396 126.052,130.396 RPG1.2@126.251,130.596
VCCBOOST: Cvcc2.2 IC2.11 | length 3.5
  Top Layer w0.3: Cvcc2.2@122.458,99.975 122.858,99.975 122.858,100.034 123.099,100.275 124.858,100.275 125.208,99.925 IC2.11@125.208,99.45
VOUT1: BRAINSUPPLY.1 BRAINSUPPLY.2 Cout2.2 IC2.5 IC2.14 R33.2 TP65.1 TP66.1 | length 10.3
  Top Layer w0.254: IC2.5@127.033,98.075 128.024,98.075 128.236,97.863 128.236,96.878 127.395,96.037
  Top Layer w0.3: IC2.14@126.608,97.35 126.608,96.593 126.862,96.339 127.093,96.339 127.395,96.037 127.558,95.874 R33.2@127.558,95.328
  Top Layer w1: Cout2.2@130.258,95.192 132.177,95.192 133.062,94.307 v2(133.062,94.18) v2(133.062,93.164)
pads on no net: BRAINSUPPLY.3 BRAINSUPPLY.4 C1.2 C2.2 C5.2 C6.2 Ccomp2.1 Ccomp3.1 CIC.2 CIN1.2 Cin2.1 CINX1.2 Cinx2.2 COUT1.2 Cout2.1 CServo.1 CSS1.2 CVCC1.2 Cvcc2.1 D7.2 D8.2 F1.2 F2.2 IC1.2 IC1.6 IC1.11 IC1.12 IC1.13 IC1.14 IC1.15 IC1.16 IC1.17 IC1.18 IC2.3 IC2.10 IC2.13 IC3.2 LED1.1 NEWCONN1.3 NEWCONN1.4 NEWCONN2.3 NEWCONN2.4 NEWCONN3.3 NEWCONN3.4 Q17.2 Q21.2 R2.2 R27.2 R35.2 R55.1 R67.1 R72.2 R79.1 R81.2 R87.1 R89.2 R93.1 RFBB1.2 RMODE1.2 RTRIP1.2 SERVOSUPPLY.3 SERVOSUPPLY.4 U13.4 U16.4 U17.1 U17.4 U17.5 U18.1 U18.4 U18.5
copper on no net: | length 17.8
  Top Layer w0.2: v1(116.928,127.997) 117.29,128.359 118.626,128.359 ; v1@117.053,131.043 117.053,130.868 117.962,129.959 118.753,129.959
  Top Layer w0.254: 121.326,127.059 123.291,127.059 ; 124.299,95.45 124.299,95.704 123.95,96.053 123.95,97.863 124.162,98.075 124.883,98.075 125.331,98.075 125.331,98.696 125.708,99.073 125.708,99.45 ; 125.308,97.35 125.308,95.196 125.315,95.196
  Top Layer w0.3: 121.326,127.059 121.326,127.559 121.326,127.959 121.326,128.359 121.326,128.759 121.326,129.159 121.326,129.559 121.326,129.959
  Bottom Layer w0.254: 149.877,107.096 149.877,108.196
  other v1: 115.342,83.857 117.439,83.857 119.536,83.857 121.633,83.857 123.73,83.857 125.827,83.857 127.924,83.857 130.021,83.857 132.118,83.857 134.215,83.857 136.312,83.857 138.409,83.857 173.993,84.905 173.993,86.99 173.993,89.074 128.49,90.37 173.993,91.159 173.993,93.244 117.568,94.487 173.993,95.329 173.993,97.413 131.919,98.117 132.808,98.117 134.713,99.133 173.993,99.498 134.586,100.022 134.078,100.53 119.858,101.275 173.993,101.583 173.993,103.667 173.993,105.752 173.993,107.837 173.993,109.921 173.993,112.006 173.993,114.091 173.993,116.175 173.993,118.26 173.993,120.345 173.993,122.429 109.31,122.916 173.993,124.514 173.993,126.599 173.993,128.683 173.993,130.768 117.055,131.045 104.166,143.202 106.263,143.202 108.36,143.202 110.457,143.202 112.554,143.202 114.651,143.202 116.748,143.202 118.844,143.202 120.941,143.202 123.038,143.202 125.135,143.202 127.232,143.202
  other v2: 131.184,105.474 131.271,106.616 155.871,108.536 150.891,109.616 150.231,110.216 132.051,110.396 149.751,111.056 131.425,111.2

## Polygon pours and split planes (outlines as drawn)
ISHUNT on Bottom Layer (solid, remove dead copper, pour order 74): 88.104,111.198 93.438,111.198 93.438,112.801 88.104,112.801
ADC1 on Top Layer (solid, remove dead copper, pour order 40): 88.104,115.008 93.438,115.008 93.438,116.532 88.104,116.532
no net on Top Layer (solid, remove dead copper, pour order 60): 80.331,80.816 178.071,80.816 178.071,147.656 80.331,147.656
no net on Bottom Layer (solid, remove dead copper, pour order 536): 76.2,76.2 184.883,76.2 184.883,150.613 76.2,150.613
SW on Top Layer (solid, remove dead copper): 119.912,131.532 120.844,131.532 121.327,132.015 122.216,132.015 123.524,133.323 123.524,140.074 122.688,141.035 119.629,141.035 119.212,140.53 119.212,132.11 119.766,131.814
+5V on Top Layer (solid, remove dead copper, pour order 2): 22 vertices, not listed, extent 104.051,126.441 115.122,141.415
OUT_BATT on Top Layer (solid, remove dead copper, pour order 4): 21 vertices, not listed, extent 116.632,117.296 141.584,142.296
+5V on Top Layer (solid, remove dead copper, pour order 6): 125.758,109.781 129.379,109.547 129.538,105.931 130.257,104.252 130.255,98.644 129.658,98.46 129.658,97.594 129.639,97.575 129.258,97.575 129.258,98.471 128.858,98.871 128.858,100.22 128.404,100.675 127.158,100.675 125.758,102.075
SW_1 on Top Layer (solid, remove dead copper, pour order 8): 115.493,112.422 120.908,112.422 121.78,111.55 121.78,107.312 121.235,106.624 115.375,106.624 113.922,108.076 113.922,110.851
VOUT1 on Top Layer (solid, remove dead copper, pour order 10): 126.898,95.96 128.219,95.96 128.617,96.593 128.932,96.961 131.595,96.961 131.768,96.788 131.768,94.8 131.443,94.475 128.8,94.475 128.318,94.975 126.958,94.975 126.858,95.075 126.858,95.92
$2N28 on Top Layer (solid, remove dead copper, pour order 12): 151.422,142.796 157.251,142.796 157.451,142.596 157.451,134.496 156.751,133.796 151.959,133.796 151.422,134.333
$2N30 on Top Layer (solid, remove dead copper, pour order 14): 167.604,142.705 173.304,142.705 173.564,142.445 173.564,134.285 173.11,133.831 168.179,133.831 167.604,134.406
OUT_BATT1 on Bottom Layer (solid, remove dead copper, pour order 52): 160.051,138.546 160.051,140.046 159.651,140.446 165.451,140.446 165.451,126.546 165.051,126.146 162.478,126.146 162.478,129.665 161.851,130.292 160.051,130.292 160.051,138.246 159.851,138.446 159.951,138.546
$1N27791 on Bottom Layer (solid, remove dead copper, pour order 54): 138.168,122.874 138.351,122.874 138.351,122.896 138.251,122.996 138.251,122.958
$1N27791 on Bottom Layer (solid, remove dead copper, pour order 56): 138.351,120.896 143.851,120.896 144.251,120.496 144.251,113.196 144.151,113.096 138.251,113.096 138.151,112.996 138.151,120.696
$1N2164 on Bottom Layer (solid, remove dead copper, pour order 58): 158.051,120.296 164.051,120.296 164.151,120.196 164.151,113.196 164.251,113.096 158.251,113.096 158.051,113.296
OUT_BATT2 on Bottom Layer (solid, remove dead copper, pour order 60): 144.051,139.496 144.725,139.496 144.051,140.169
OUT_BATT2 on Bottom Layer (solid, remove dead copper, pour order 62): 143.989,140.512 150.083,140.512 150.083,136.328 148.432,131.833 148.432,125.985 147.473,126.001 146.115,125.42 142.964,125.383 142.551,125.796 142.551,134.096 143.989,135.534
UBATT on Bottom Layer (solid, remove dead copper, pour order 64): 138.132,106.296 138.132,103.948 141.902,99.847 157.802,99.847 159.924,101.969 159.924,107.296 158.051,107.296 157.413,106.658 157.413,102.977 156.032,101.596 143.351,101.596 140.305,104.642 140.305,105.819 139.632,106.296
OUT_BATT on Bottom Layer (solid, remove dead copper, pour order 66): 143.07,94.415 143.462,94.023 149.263,94.023 149.959,94.41 149.959,95.01 148.97,95.999 143.593,95.999 143.07,95.579
OUT_BATT on Top Layer (solid, remove dead copper, pour order 32): 144.803,94.236 144.803,95.633 144.487,96.128 142.859,96.128 141.605,97.098 141.605,118.895 134.172,118.824 133.199,117.359 136.284,113.597 136.364,96.974 139.373,93.965 144.532,93.965
+5V on Bottom Layer (solid, remove dead copper, pour order 70): 104.673,141.369 107.729,141.369 108.098,140.911 108.098,117.366 108.932,116.532 111.373,116.532 111.726,116.271 111.726,113.78 111.288,113.595 107.17,113.595 104.233,116.532 104.233,140.861
+5V on Top Layer (solid, remove dead copper, pour order 36): 108.551,114.112 108.551,116.174 109.314,116.532 127.818,116.532 129.551,114.799 129.551,110.353 128.236,109.039 126.204,109.039 125.696,109.547 125.696,112.722 124.807,113.611 109.324,113.611
+5V on Bottom Layer (solid, remove dead copper, pour order 78): 87.729,91.636 88.058,91.883 105.822,91.956 107.662,90.116 107.662,88.592 107.154,88.084 101.123,88.084 99.166,90.041 88.252,90.041 87.723,90.243
+5V on Top Layer (solid, remove dead copper, pour order 44): 87.723,140.916 88.231,141.424 107.992,141.424 108.539,140.876 108.539,139.125 107.916,138.503 104.21,138.503 102.813,139.9 88.104,139.9 87.723,140.281
+5V on Top Layer (solid, remove dead copper, pour order 46): 87.607,132.915 87.988,133.296 100.688,133.296 102.339,131.645 106.076,131.645 107.419,131.993 107.419,129.012 106.214,129.616 101.061,129.616 99.16,131.518 88.242,131.518 87.607,132.153
+5V on Top Layer (solid, remove dead copper, pour order 48): 87.876,124.518 88.386,125.028 101.415,125.028 102.599,126.212 102.599,129.041 101.432,130.207 101.627,130.402 105.375,130.402 104.155,129.182 104.155,125.293 102.122,123.26 88.28,123.26 87.876,123.663
+5V on Top Layer (solid, remove dead copper, pour order 50): 107.281,116.532 112.361,116.532 112.996,115.897 112.996,114.373 111.333,112.709 111.333,92.725 110.86,92.152 108.678,92.152 107.789,92.647 107.789,112.71 106.646,114.246
+5V on Top Layer (solid, remove dead copper, pour order 52): 87.977,99.716 88.37,100.149 107.154,100.149 108.551,101.546 108.551,97.228 108.424,97.101 107.154,98.371 88.384,98.371 87.977,98.625
VOUT1 on Bottom Layer (solid, remove dead copper, pour order 90): 133.443,92.959 133.152,92.656 120.997,92.656 107.027,106.626 88.739,106.626 87.723,107.071 87.723,108.119 88.723,108.404 108.17,108.404 121.886,94.688 133.189,94.688 133.443,94.434
+5V on Top Layer (solid, remove dead copper, pour order 56): 87.985,95.924 88.485,96.339 107.027,96.339 108.551,97.863 108.551,93.267 107.049,94.561 88.731,94.561 87.977,95.069
+5V on Bottom Layer (solid, remove dead copper, pour order 94): 109.371,93.956 110.691,93.956 111.171,93.476 111.171,90.23 109.045,88.104 103.763,88.104 103.611,88.256 103.611,90.716 104.331,91.436 105.294,91.436 107.831,93.973 109.354,93.973
no net on Bottom Layer (solid, remove dead copper, pour order 98): 737 vertices, not listed, extent 108.745,83.129 173.248,142.775
no net on Bottom Layer (solid, remove dead copper, pour order 100): 175 vertices, not listed, extent 87.075,84.783 144.11,115.498
no net on Bottom Layer (solid, remove dead copper, pour order 102): 490 vertices, not listed, extent 137.796,95.739 167.397,125.642
no net on Bottom Layer (solid, remove dead copper, pour order 104): 152 vertices, not listed, extent 134.66,123.807 150.34,142.902
no net on Bottom Layer (solid, remove dead copper, pour order 106): 26 vertices, not listed, extent 103.977,113.338 111.983,141.626
no net on Bottom Layer (solid, remove dead copper, pour order 108): 37 vertices, not listed, extent 87.075,87.827 111.428,94.23
no net on Bottom Layer (solid, remove dead copper, pour order 110): 22 vertices, not listed, extent 157.795,109.39 164.522,123.536
no net on Bottom Layer (solid, remove dead copper, pour order 112): 28 vertices, not listed, extent 117.445,125.589 126.158,131.445
no net on Bottom Layer (solid, remove dead copper, pour order 114): 167.398,139.646 cw(c170.654,139.646) 170.654,142.902 cw(c170.654,139.646) 173.911,139.646 cw(c170.654,139.646) 170.654,136.389 cw(c170.654,139.646)
no net on Bottom Layer (solid, remove dead copper, pour order 116): 154.398,136.389 cw(c154.398,139.646) 151.142,139.646 cw(c154.398,139.646) 154.398,142.902 cw(c154.398,139.646) 157.655,139.646 cw(c154.398,139.646)
no net on Bottom Layer (solid, remove dead copper, pour order 118): 135.648,139.646 cw(c138.904,139.646) 138.904,142.902 cw(c138.904,139.646) 142.161,139.646 cw(c138.904,139.646) 138.904,136.389 cw(c138.904,139.646)
no net on Bottom Layer (solid, remove dead copper, pour order 120): 131.538,136.543 cw(c131.538,139.646) 128.436,139.646 cw(c131.538,139.646) 131.538,142.748 cw(c131.538,139.646) 134.641,139.646 cw(c131.538,139.646)
no net on Bottom Layer (solid, remove dead copper, pour order 122): 36 vertices, not listed, extent 142.814,93.766 153.127,96.98
no net on Bottom Layer (solid, remove dead copper, pour order 124): 117.015,88.05 112.715,88.05 cw(c112.715,88.153) 112.612,88.153 112.612,90.203 cw(c112.715,90.203) 112.715,90.306 117.015,90.306 cw(c117.015,90.203) 117.117,90.203 117.117,88.153 cw(c117.015,88.153)
no net on Bottom Layer (solid, remove dead copper, pour order 126): 99.547,135.372 cw(c99.547,136.879) 98.041,136.879 cw(c99.547,136.879) 99.547,138.385 cw(c99.547,136.879) 101.054,136.879 cw(c99.547,136.879)
no net on Bottom Layer (solid, remove dead copper, pour order 128): 24 vertices, not listed, extent 162.506,93.74 166.805,95.452
no net on Bottom Layer (solid, remove dead copper, pour order 130): 87.075,131.485 87.075,133.285 cw(c87.331,133.285) 87.331,133.541 89.131,133.541 cw(c89.131,133.285) 89.388,133.285 89.388,131.485 cw(c89.131,131.485) 89.131,131.228 87.331,131.228 cw(c87.331,131.485)
no net on Bottom Layer (solid, remove dead copper, pour order 132): 89.131,122.951 87.331,122.951 cw(c87.331,123.208) 87.075,123.208 87.075,125.008 cw(c87.331,125.008) 87.331,125.265 89.131,125.265 cw(c89.131,125.008) 89.388,125.008 89.388,123.208 cw(c89.131,123.208)
no net on Bottom Layer (solid, remove dead copper, pour order 134): 89.131,139.505 87.331,139.505 cw(c87.331,139.762) 87.075,139.762 87.075,141.562 cw(c87.331,141.562) 87.331,141.818 89.131,141.818 cw(c89.131,141.562) 89.388,141.562 89.388,139.762 cw(c89.131,139.762)
no net on Bottom Layer (solid, remove dead copper, pour order 136): 89.131,114.675 87.331,114.675 cw(c87.331,114.931) 87.075,114.931 87.075,116.731 cw(c87.331,116.731) 87.331,116.988 89.131,116.988 cw(c89.131,116.731) 89.388,116.731 89.388,114.931 cw(c89.131,114.931)
no net on Bottom Layer (solid, remove dead copper, pour order 138): 93.311,122.951 cw(c93.311,124.108) 92.155,124.108 cw(c93.311,124.108) 93.311,125.265 cw(c93.311,124.108) 94.468,124.108 cw(c93.311,124.108)
no net on Bottom Layer (solid, remove dead copper, pour order 140): 92.155,132.385 cw(c93.311,132.385) 93.311,133.541 cw(c93.311,132.385) 94.468,132.385 cw(c93.311,132.385) 93.311,131.228 cw(c93.311,132.385)
no net on Bottom Layer (solid, remove dead copper, pour order 142): 92.155,140.662 cw(c93.311,140.662) 93.311,141.818 cw(c93.311,140.662) 94.468,140.662 cw(c93.311,140.662) 93.311,139.505 cw(c93.311,140.662)
no net on Bottom Layer (solid, remove dead copper, pour order 144): 87.075,98.377 87.075,100.177 cw(c87.331,100.177) 87.331,100.434 89.131,100.434 cw(c89.131,100.177) 89.388,100.177 89.388,98.377 cw(c89.131,98.377) 89.131,98.121 87.331,98.121 cw(c87.331,98.377)
no net on Bottom Layer (solid, remove dead copper, pour order 146): 92.155,95.467 cw(c93.311,95.467) 93.311,96.624 cw(c93.311,95.467) 94.468,95.467 cw(c93.311,95.467) 93.311,94.311 cw(c93.311,95.467)
no net on Bottom Layer (solid, remove dead copper, pour order 148): 93.311,114.675 cw(c93.311,115.831) 92.155,115.831 cw(c93.311,115.831) 93.311,116.988 cw(c93.311,115.831) 94.468,115.831 cw(c93.311,115.831)
no net on Bottom Layer (solid, remove dead copper, pour order 150): 88.231,94.311 cw(c88.231,95.467) 87.075,95.467 cw(c88.231,95.467) 88.231,96.624 cw(c88.231,95.467) 89.388,95.467 cw(c88.231,95.467)
no net on Bottom Layer (solid, remove dead copper, pour order 152): 93.311,98.121 cw(c93.311,99.277) 92.155,99.277 cw(c93.311,99.277) 93.311,100.434 cw(c93.311,99.277) 94.468,99.277 cw(c93.311,99.277)
no net on Bottom Layer (solid, remove dead copper, pour order 154): 87.229,128.575 cw(c88.231,128.575) 88.231,129.577 cw(c88.231,128.575) 89.234,128.575 cw(c88.231,128.575) 88.231,127.572 cw(c88.231,128.575)
no net on Bottom Layer (solid, remove dead copper, pour order 156): 92.309,128.575 cw(c93.311,128.575) 93.311,129.577 cw(c93.311,128.575) 94.314,128.575 cw(c93.311,128.575) 93.311,127.572 cw(c93.311,128.575)
no net on Bottom Layer (solid, remove dead copper, pour order 158): 88.231,119.295 cw(c88.231,120.298) 87.229,120.298 cw(c88.231,120.298) 88.231,121.301 cw(c88.231,120.298) 89.234,120.298 cw(c88.231,120.298)
no net on Bottom Layer (solid, remove dead copper, pour order 160): 93.311,135.849 cw(c93.311,136.852) 92.309,136.852 cw(c93.311,136.852) 93.311,137.854 cw(c93.311,136.852) 94.314,136.852 cw(c93.311,136.852)
no net on Bottom Layer (solid, remove dead copper, pour order 162): 87.229,136.852 cw(c88.231,136.852) 88.231,137.854 cw(c88.231,136.852) 89.234,136.852 cw(c88.231,136.852) 88.231,135.849 cw(c88.231,136.852)
no net on Bottom Layer (solid, remove dead copper, pour order 164): 93.311,119.295 cw(c93.311,120.298) 92.309,120.298 cw(c93.311,120.298) 93.311,121.301 cw(c93.311,120.298) 94.314,120.298 cw(c93.311,120.298)
no net on Bottom Layer (solid, remove dead copper, pour order 166): 92.309,87.191 cw(c93.311,87.191) 93.311,88.193 cw(c93.311,87.191) 94.314,87.191 cw(c93.311,87.191) 93.311,86.188 cw(c93.311,87.191)
no net on Bottom Layer (solid, remove dead copper, pour order 168): 88.231,102.742 cw(c88.231,103.744) 87.229,103.744 cw(c88.231,103.744) 88.231,104.747 cw(c88.231,103.744) 89.234,103.744 cw(c88.231,103.744)
no net on Bottom Layer (solid, remove dead copper, pour order 170): 88.231,86.188 cw(c88.231,87.191) 87.229,87.191 cw(c88.231,87.191) 88.231,88.193 cw(c88.231,87.191) 89.234,87.191 cw(c88.231,87.191)
no net on Bottom Layer (solid, remove dead copper, pour order 172): 93.311,102.742 cw(c93.311,103.744) 92.309,103.744 cw(c93.311,103.744) 93.311,104.747 cw(c93.311,103.744) 94.314,103.744 cw(c93.311,103.744)
no net on Bottom Layer (solid, remove dead copper, pour order 174): 165.66,103.063 165.66,104.196 cw(c165.763,104.196) 165.763,104.298 167.14,104.298 cw(c167.14,104.196) 167.243,104.196 167.243,103.063 cw(c167.14,103.063) 167.14,102.961 165.763,102.961 cw(c165.763,103.063)
no net on Bottom Layer (solid, remove dead copper, pour order 176): 154.849,102.907 154.849,104.284 cw(c154.951,104.284) 154.951,104.387 156.084,104.387 cw(c156.084,104.284) 156.186,104.284 156.186,102.907 cw(c156.084,102.907) 156.084,102.805 154.951,102.805 cw(c154.951,102.907)
no net on Bottom Layer (solid, remove dead copper, pour order 178): 162.145,100.641 162.145,101.251 cw(c162.401,101.251) 162.401,101.507 163.376,101.507 cw(c163.376,101.251) 163.633,101.251 163.633,100.641 cw(c163.376,100.641) 163.376,100.384 162.401,100.384 cw(c162.401,100.641)
no net on Bottom Layer (solid, remove dead copper, pour order 180): 129.406,117.701 cw(c129.795,117.701) 129.795,118.09 131.109,118.09 cw(c131.109,117.701) 131.499,117.701 cw(c131.109,117.701) 131.109,117.311 129.795,117.311 cw(c129.795,117.701)
no net on Bottom Layer (solid, remove dead copper, pour order 182): 153.649,105.896 153.649,106.596 cw(c153.751,106.596) 153.751,106.698 154.751,106.698 cw(c154.751,106.596) 154.854,106.596 154.854,105.896 cw(c154.751,105.896) 154.751,105.793 153.751,105.793 cw(c153.751,105.896)
no net on Bottom Layer (solid, remove dead copper, pour order 184): 154.751,107.693 153.751,107.693 cw(c153.751,107.796) 153.649,107.796 153.649,108.496 cw(c153.751,108.496) 153.751,108.598 154.751,108.598 cw(c154.751,108.496) 154.854,108.496 154.854,107.796 cw(c154.751,107.796)
no net on Bottom Layer (solid, remove dead copper, pour order 186): 134.349,104.096 134.349,105.096 cw(c134.451,105.096) 134.451,105.198 135.151,105.198 cw(c135.151,105.096) 135.254,105.096 135.254,104.096 cw(c135.151,104.096) 135.151,103.993 134.451,103.993 cw(c134.451,104.096)
no net on Bottom Layer (solid, remove dead copper, pour order 188): 133.252,103.993 132.552,103.993 cw(c132.552,104.096) 132.449,104.096 132.449,105.096 cw(c132.552,105.096) 132.552,105.198 133.252,105.198 cw(c133.252,105.096) 133.354,105.096 133.354,104.096 cw(c133.252,104.096)
no net on Bottom Layer (solid, remove dead copper, pour order 190): 154.217,109.839 154.217,110.646 cw(c154.319,110.646) 154.319,110.748 155.183,110.748 cw(c155.183,110.646) 155.286,110.646 155.286,109.839 cw(c155.183,109.839) 155.183,109.737 154.319,109.737 cw(c154.319,109.839)
no net on Bottom Layer (solid, remove dead copper, pour order 192): 127.19,116.546 127.19,117.352 cw(c127.292,117.352) 127.292,117.455 128.156,117.455 cw(c128.156,117.352) 128.259,117.352 128.259,116.546 cw(c128.156,116.546) 128.156,116.443 127.292,116.443 cw(c127.292,116.546)
no net on Bottom Layer (solid, remove dead copper, pour order 194): 147.21,118.303 146.346,118.303 cw(c146.346,118.406) 146.244,118.406 146.244,119.212 cw(c146.346,119.212) 146.346,119.315 147.21,119.315 cw(c147.21,119.212) 147.313,119.212 147.313,118.406 cw(c147.21,118.406)
no net on Bottom Layer (solid, remove dead copper, pour order 196): 135.517,120.139 135.517,120.946 cw(c135.619,120.946) 135.619,121.048 136.483,121.048 cw(c136.483,120.946) 136.586,120.946 136.586,120.139 cw(c136.483,120.139) 136.483,120.037 135.619,120.037 cw(c135.619,120.139)
no net on Bottom Layer (solid, remove dead copper, pour order 198): 149.492,122.864 149.492,123.728 cw(c149.595,123.728) 149.595,123.83 150.401,123.83 cw(c150.401,123.728) 150.504,123.728 150.504,122.864 cw(c150.401,122.864) 150.401,122.761 149.595,122.761 cw(c149.595,122.864)
no net on Bottom Layer (solid, remove dead copper, pour order 200): 166.555,95.493 165.755,95.493 cw(c165.755,95.595) 165.652,95.595 165.652,96.395 cw(c165.755,96.395) 165.755,96.498 166.555,96.498 cw(c166.555,96.395) 166.657,96.395 166.657,95.595 cw(c166.555,95.595)
no net on Bottom Layer (solid, remove dead copper, pour order 202): 152.385,125.904 151.485,125.904 cw(c151.485,126.006) 151.383,126.006 151.383,126.706 cw(c151.485,126.706) 151.485,126.809 152.385,126.809 cw(c152.385,126.706) 152.488,126.706 152.488,126.006 cw(c152.385,126.006)
no net on Bottom Layer (solid, remove dead copper, pour order 204): 135.041,123.127 134.341,123.127 cw(c134.341,123.23) 134.239,123.23 134.239,124.13 cw(c134.341,124.13) 134.341,124.232 135.041,124.232 cw(c135.041,124.13) 135.144,124.13 135.144,123.23 cw(c135.041,123.23)
no net on Bottom Layer (solid, remove dead copper, pour order 206): 83.51,82.752 cw(c83.51,82.854) 83.408,82.854 83.408,144.137 cw(c83.51,144.137) 83.51,144.239 174.793,144.239 cw(c174.793,144.137) 174.895,144.137 174.895,82.854 cw(c174.793,82.854) 174.793,82.752
no net on Bottom Layer (solid, remove dead copper, pour order 208): 103 vertices, not listed, extent 128.157,108.602 134.215,115.516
